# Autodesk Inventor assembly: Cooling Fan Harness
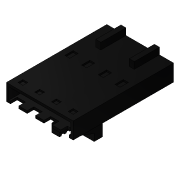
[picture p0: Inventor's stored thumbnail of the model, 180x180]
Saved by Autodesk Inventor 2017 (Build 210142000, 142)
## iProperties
Created: 2007-02
Part Number: Cooling Fan Harness
Document SubType Name: Assembly
Designer: DanielSeverino
Author: DanielSeverino
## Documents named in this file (2)
- C:\Users\DanielSeverino\Desktop\01\Cooling Fan Harness.iam
- C:\Users\DanielSeverino\Desktop\01\Fan Connector.ipt
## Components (1 placed, 1 different names)
1. Fan Connector:1
